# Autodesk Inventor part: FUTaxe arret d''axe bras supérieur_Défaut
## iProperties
Shininess: 64.0
Length Units: 11269
Angle Units: 11279
Time Units: 11290
Mass Units: 11283
Length Display Precision: 3
Angle Display Precision: 2
Compacted: True
Part Number: FUTaxe arret d''axe bras supérieur_Défaut
Document SubType Name: Modeling
Created: 2006-11
Material: Par défaut
Designer: profs_sti
Density: 0.0
Volumn: 0.0
Area: 0.0
PropertySet Name: Model Information
Control State: 0
Master: False
Checked Out: False
Author: profs_sti
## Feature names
1. Base1
